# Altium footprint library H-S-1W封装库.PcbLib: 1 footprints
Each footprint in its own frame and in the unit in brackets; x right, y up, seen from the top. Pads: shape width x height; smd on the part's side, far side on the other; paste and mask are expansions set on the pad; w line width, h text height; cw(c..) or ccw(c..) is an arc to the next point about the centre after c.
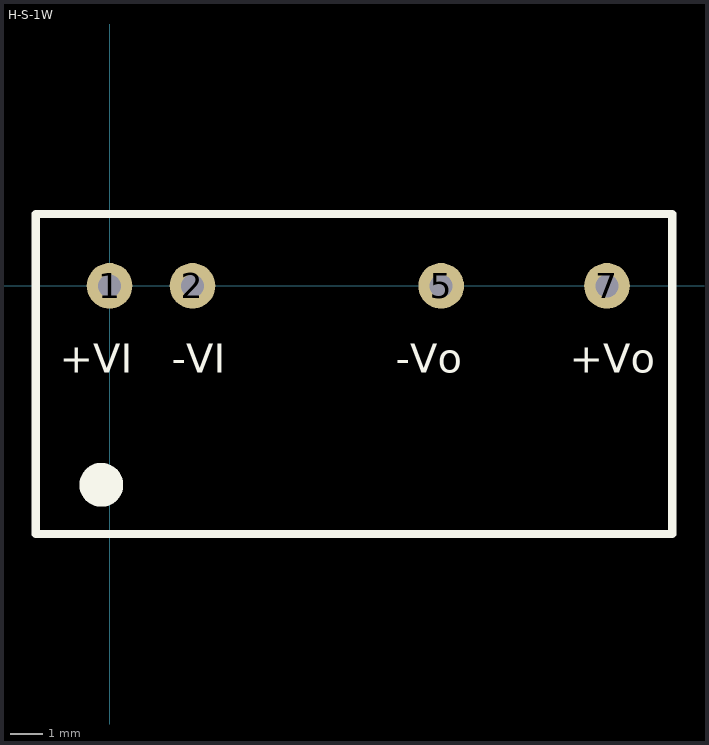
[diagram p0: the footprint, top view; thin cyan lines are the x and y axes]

## H-S-1W [mm]
pads (4):
  round 1.4 hole 0.7: 1(0,0) 2(2.54,0) 5(10.16,0) 7(15.24,0)
Top Overlay:
  circle w0.98: c-0.254,-6.096 r0.18
  lines w0.254: -2.26,-7.6 17.24,-7.6 17.24,2.2 -2.26,2.2 -2.26,-7.6
  text "+Vo" at 14.097,-2.667 h0.9
  text "-Vo" at 8.763,-2.667 h0.9
  text "+VI" at -1.524,-2.667 h0.9
  text "-VI" at 1.905,-2.667 h0.9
